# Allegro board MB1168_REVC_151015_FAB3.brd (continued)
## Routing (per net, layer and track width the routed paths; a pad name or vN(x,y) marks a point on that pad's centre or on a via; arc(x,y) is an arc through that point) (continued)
+3V3_PG: length 71.5
  TOP w0.127: U20.3 25.46,47.05 25.27,46.86 R148.2 25.53,45.59 26.29,46.35 29.08,46.35 30.86,48.13 49.4,48.13 50.67,46.86 75.82,46.86 76.45,46.23 87.76,46.23 90.17,43.81 R150.1
+3V3_STLINK: length 103.8
  TOP w0.203: 44.68,25.09 44.68,26.38 U24.9
  TOP w0.279: v1(40.26,25.27) 40.68,25.7 U24.1 ; U24.36 40.68,35.64 39.88,36.45 C97.2 ; C103.2 50.25,33.48 U24.24 ; U26.8 50.06,26.95 49.91,26.8 ; C107.2 36.62,27.98 U24.48
  TOP w0.508: v1(47.27,24.49) 47.27,23.9 C115.1 46.99,23.67 46,24.66 45.11,24.66 44.68,25.09 ; C107.2 v1(36.58,28.7) ; U16.5 24.2,60.51 C73.1 ; U16.5 22.28,61.01 ; U16.5 22.28,60.02 ; C73.1 v1(24.26,61.47) ; C73.1 23.67,60.45 ; C73.1 24.84,60.45 ; v1(52.82,15.63) 52.71,15.63 51.82,14.73 46.74,14.73 R208.2 37.97,13.72 JP13.1 ; C97.2 v1(39.88,37.72) ; C103.2 v1(50.29,34.39) ; 49.91,26.8 v1(49.91,26.04) ; T14.3 v1(99.95,16.51) ; R184.2 v1(45.85,21.79)
  BOTTOM w0.508: v1(45.85,21.79) 46.69,20.95 51.23,20.95 52.48,19.71 52.48,15.98 v1(52.82,15.63) 53.47,14.99 67.31,14.99 68.71,13.59 78.49,13.59 81.41,16.51 v1(99.95,16.51)
  vias: v1(25.27,61.59) v1(25.27,60.33)
+5V: length 70.9
  TOP w0.279: U28.8 28.79,20.36 29.72,19.43 C117.2
  TOP w0.508: LD7.1 v1(13.59,4.45) ; C82.1 96.95,44.58 ; C82.1 96.14,45.52 ; C82.1 95.33,44.58 ; C82.1 96.14,43.64 ; R156.1 v1(91.69,39.75) ; R151.1 v1(76.96,41.91) ; v1(17.27,49.53) 12.95,49.53 JP11.1 ; C79.1 21.08,51.74 ; C79.1 22.02,50.93 ; C79.1 20.14,50.93 ; C79.1 21.08,50.11 ; 96.18,42.63 U22.6 96.71,42.22 ; SB40.1 v1(88.64,29.09) ; 23.15,50.58 U20.6 23.56,51.12 ; D7.1 v1(31.9,31.51) ; TP22.1 R153.2 ; v1(22.61,43.05) 24.26,43.05 R148.1 ; C117.2 v1(30.61,18.8)
  BOTTOM w0.508: JP11.7 JP11.5 JP11.3 JP11.1 12.45,46.23 12.45,44.07 TP22.1 ; v1(30.61,18.8) 30.73,18.67 30.73,15.62 28.83,13.72 24.89,13.72 15.62,4.45 v1(13.59,4.45)
  vias: v1(18.03,49.53) v1(18.8,49.53) v1(95.89,46.23) v1(96.77,46.23)
AGND: length 24.7
  TOP w0.356: U4.4 107.66,140.93 v1(108.2,141.48) ; U3.4 v1(105.82,147.91)
  TOP w0.508: C9.2 106.05,144.7 ; C9.2 105.23,143.76 ; C9.2 106.86,143.76 ; C9.2 106.05,142.82 ; C19.2 v1(107.7,135.38) ; C17.1 v1(97.79,137.29) ; C18.2 v1(96.14,135.38) ; SB20.2 v1(105.54,130.05) ; SB3.2 v1(94.61,153.67) ; R23.2 v1(98.93,142.49) ; R21.2 v1(110.11,145.41) ; C8.1 v1(97.79,144.78) ; SB2.2 v1(94.61,156.46) ; C1.1 v1(112.27,156.21) ; 93.47,149.78 L1.2 ; L1.2 93.47,150.95 ; L1.2 v1(94.49,150.37) ; R16.2 v1(95.63,146.18) ; SB21.2 v1(108.46,130.05) ; SB19.2 v1(99.95,130.05) ; U1.1 v1(108.08,152.78) ; SB1.2 v1(94.49,160.15)
  vias: v1(93.73,163.07) v1(93.98,171.32) v1(100.71,150.24) v1(101.35,159.89) v1(101.98,171.2) v1(105.79,142.49) v1(106.93,142.49) v1(112.9,171.07) v1(113.16,159.38)
D5V: length 89
  TOP w0.508: v1(20.95,62.74) 20.95,62.36 20.57,61.98 17.27,61.98 16,60.71 14.48,60.71 12.57,58.8 10.29,58.8 v1(9.78,58.29) ; D5.1 8.13,54.6 8.13,53.21 v1(8.15,53.19) 8.13,53.16 8.13,50.8 9.65,49.28 9.65,46.99 11.05,45.59 JP11.2
  BOTTOM w0.508: v1(8.15,53.19) 8.13,53.21 8.13,56.64 v1(9.78,58.29) ; v1(20.95,62.74) 21.08,62.87 21.08,64.14 20.7,64.52 20.7,81.92 20.19,82.42 20.19,84.58 20.7,85.09 20.7,104.65 19.94,105.41 19.94,115.82 20.95,116.84 22.86,116.84 CN4.24
GND: length 585.9
  TOP w0.254: U17.4 31.74,55.84 v1(32,56.11) ; U12.4 93.32,94.55 93.32,93.9 v1(93.34,93.88) ; U17.3 31.24,55.86 v1(30.99,56.11) ; U19.4 39.74,55.13 v1(40.26,54.61) ; v1(35.81,57.4) 35.68,57.54 U18.6
  TOP w0.279: v1(63.25,137.03) 63.12,136.91 63.12,136.53 62.65,136.06 U5.27 ; v1(26.54,28.7) 26.84,28.41 U28.4 ; U25.8 v1(66.56,33.92) ; U5.74 49.39,121.79 47.88,121.79 v1(47.75,121.67) ; v1(62.48,118.11) 62.65,118.28 U5.99 ; U26.4 v1(52.2,29.45) ; U24.8 v1(44.18,27.8) ; U18.3 35.68,55.88 v1(35.94,56.13) 36.18,55.89 U18.4 ; U13.4 19.17,86.22 v1(19.3,86.36) ; U5.20 65.97,130.75 v1(66.29,130.43) 66.12,130.25 U5.19 ; v1(73.03,33.15) 72.86,32.98 U25.47 ; U24.35 41.18,35.9 40.89,36.2 C97.1 ; U10.2 v1(9.4,148.46) ; U25.23 64.23,28.48 v1(64.26,28.45) ; v1(37.85,28.83) 38.19,28.48 U24.47 ; v1(49.23,32.69) 48.93,32.98 U24.23 ; v1(69.85,25.27) 69.56,25.56 U25.35 ; U23.4 88.86,35.27 v1(89.15,35.56) ; U5.49 v1(51.65,133.57)
  TOP w0.305: U8.25 v1(90.29,102.25) ; U8.12 94.61,107.45 94.36,107.19 v1(94.36,107.19) ; v1(90.42,103.25) 90.13,103.55 U8.23 ; U7.4 v1(16.24,110.48) ; U8.4 v1(97.27,102.25) ; U7.25 v1(23.51,110.48) ; U7.12 v1(16.13,105.28) ; U7.23 23.88,109.18 23.5,109.56 v1(23.5,109.6)
  TOP w0.356: U21.4 v1(86.78,42.38) ; U15.2 v1(101.59,76.08)
  TOP w0.381: CN9.5 5.24,146.91 v1(5.59,146.56)
  TOP w0.457: U22.2 v1(94.74,41.27)
  TOP w0.508: 20.14,48.13 C79.2 ; C79.2 22.02,48.13 ; C79.2 21.08,47.32 ; C79.2 21.08,48.95 ; 103.96,123.9 CN7.10 ; CN7.10 105.28,126.37 ; CN7.10 105.28,121.44 ; CN7.10 106.6,123.9 ; 110.55,83.95 111.49,83.95 ; 110.55,83.95 110.55,83.01 ; 110.55,83.95 109.61,83.95 ; 110.55,83.95 110.55,84.89 ; R115.1 v1(100.97,63.75) ; 110.55,63.63 111.49,63.63 ; 110.55,63.63 110.55,64.57 ; 110.55,63.63 109.61,63.63 ; 110.55,63.63 110.55,62.69 ; CN4.1 22.43,146.05 ; CN4.1 20.75,146.05 ; CN4.1 21.59,146.89 ; CN4.1 21.59,145.21 ; CN12.18 110.55,67.11 ; CN12.18 110.55,65.23 ; CN12.18 109.61,66.17 ; CN12.18 111.49,66.17 ; 28.63,49.02 C81.2 ; C81.2 29.08,48.56 ; C81.2 29.54,49.02 ; 93.55,27.94 CN16.11 ; CN16.11 94.49,28.88 ; CN16.11 95.43,27.94 ; CN16.11 94.49,27 ; LD6.1 v1(49.14,13.58) ; R185.2 48.59,22.61 ; R185.2 47.68,22.61 ; R185.2 v1(48.13,21.82) ; 39.04,22.61 R182.1 ; R182.1 39.95,22.61 ; R182.1 v1(39.5,21.77) ; CN9.8 5.08,150.71 ; CN9.8 4.15,151.64 ; CN9.8 3.22,150.71 ; C101.1 78.74,32.89 v1(79.12,32.89) ; CN4.12 24.13,134.19 ; CN4.12 23.29,133.35 ; CN4.12 24.13,132.51 ; CN4.12 24.97,133.35 ; RV1.2 26.29,6.48 ; RV1.2 26.29,4.95 ; RV1.2 27.05,5.71 ; RV1.2 25.53,5.71 ; 109.61,81.41 CN12.6 ; CN12.6 110.55,82.35 ; CN12.6 111.49,81.41 ; CN12.6 110.55,80.47 ; CN11.5 v1(90.04,81.53) ; R169.1 v1(76.96,32.13) ; C80.2 28.25,48.64 ; C80.2 26.62,48.64 ; C80.2 27.43,47.89 ; C51.2 v1(99.31,102.62) ; C51.2 99.31,101.4 ; C51.2 99.77,101.85 ; 110.55,78.87 111.49,78.87 ; 110.55,78.87 110.55,79.81 ; 110.55,78.87 109.61,78.87 ; 110.55,78.87 110.55,77.93 ; 23.75,8.26 24.51,8.26 ; 23.75,8.26 23.75,9.02 ; 23.75,8.26 23.75,7.49 ; 23.75,8.26 22.99,8.26 ; CN16.12 97.97,27.94 ; CN16.12 97.03,27 ; CN16.12 96.09,27.94 ; CN16.12 97.03,28.88 ; R183.1 v1(40.77,21.41) ; R183.1 41.35,22.35 ; R183.1 40.18,22.35 ; R175.2 35.56,30.56 ; R175.2 35.56,29.64 ; R175.2 v1(34.67,30.1) ; CN4.11 21.59,134.19 ; CN4.11 22.43,133.35 ; CN4.11 21.59,132.51 ; CN4.11 20.75,133.35 ; SB20.1 v1(105.41,128.52) ; R74.1 8.64,147.14 ; R74.1 v1(9.78,146.56) ; R74.1 8.64,145.97 ; R167.2 v1(91.31,33.4) ; C115.2 47.45,22.61 ; C115.2 46.53,22.61 ; C115.2 v1(46.99,21.82) ; v1(72.14,125.22) 71.25,125.22 R46.1 ; C103.1 v1(51.31,34.39) ; v1(92.58,36.58) 93.85,36.58 v1(93.85,35.43) ; R113.1 101.73,66.75 ; R113.1 v1(100.97,66.29) ; R113.1 101.73,65.84 ; R172.2 v1(52.2,31.5) ; R76.2 v1(61.21,102.62) ; v1(72.39,126.24) C28.1 ; U29.4 51.56,45.21 v1(51.94,44.83) ; v1(75.31,126.75) 75.31,126.87 74.93,127.25 C27.2 ; B1.4 v1(50.1,5.52) ; B1.4 51.62,4.84 ; B1.4 52.56,5.52 ; B1.4 51.62,6.21 ; C93.1 v1(65.28,40.01) ; 22.6,152.53 U2.6 ; U2.6 23.67,152.98 ; U2.6 23.67,152.07 ; U2.6 v1(25.15,152.53) ; SW1.3 30.23,130.68 ; SW1.3 31.12,129.79 ; SW1.3 29.34,129.79 ; SW1.3 30.23,128.9 ; R123.2 v1(58.93,57.91) ; R206.2 v1(102.23,12.06) ; R206.2 101.78,12.83 ; R206.2 102.69,12.83 ; C36.2 36.18,115.95 ; C36.2 35.56,116.54 ; C36.2 35.56,115.37 ; C12.1 v1(56.39,145.29) ; 29.34,158.7 CN1.7 ; CN1.7 v1(27.69,159.38) ; CN1.7 30.66,159.38 ; CN1.7 29.34,160.07 ; C54.1 v1(40.64,42.67) ; R102.1 v1(49.53,76.83) ; C10.1 v1(53.34,145.29) ; 7.7,137.72 CN6.11 ; CN6.11 9.02,140.18 ; CN6.11 9.02,135.25 ; CN6.11 10.34,137.72 ; C89.1 v1(90.17,39.62) ; R173.1 35.56,31.7 ; R173.1 v1(34.67,31.24) ; R173.1 35.56,30.78 ; SB3.1 v1(90.68,153.67) ; C107.1 35.56,28.4 ; C107.1 35.56,27.48 ; C107.1 v1(34.67,27.94) ; v1(68.96,131.06) 69.09,130.94 69.85,130.94 ; C67.1 v1(15.62,86.23) ; C41.2 38.61,112.9 39.37,112.14 v1(39.5,112.14) ; C29.1 v1(42.67,124.08) ; v1(18.54,67.06) 18.54,66.42 R112.1 ; CN12.14 111.49,71.25 ; CN12.14 110.55,70.31 ; CN12.14 109.61,71.25 ; CN12.14 110.55,72.19 ; 92.53,44.58 C82.2 ; C82.2 93.34,43.64 ; C82.2 93.34,45.52 ; C82.2 94.16,44.58 ; CN7.5 103.89,117.98 ; CN7.5 103.89,115.85 ; CN7.5 105.08,116.92 ; CN7.5 102.69,116.92 ; C48.2 50.67,43.56 v1(51.18,44.07) ; C46.1 45.92,99.69 ; C46.1 45.01,99.69 ; C46.1 45.47,99.24 ; U2.4 v1(27.43,153.8) ; C113.1 v1(43.56,21.77) ; CN11.3 v1(90.04,82.8) ; 109.61,76.33 CN12.10 ; CN12.10 110.55,77.27 ; CN12.10 110.55,75.39 ; CN12.10 111.49,76.33 ; 103.96,98.86 CN7.11 ; CN7.11 105.28,96.39 ; CN7.11 105.28,101.32 ; CN7.11 106.6,98.86 ; 24.69,19.05 R196.2 ; R196.2 25.86,19.05 ; R196.2 v1(25.27,19.94) ; C24.2 70.99,130.18 v1(68.96,130.18) ; 8.26,150.11 8.71,150.11 ; 8.26,150.11 v1(8.26,150.88) ; 8.26,150.11 8.26,149.66 ; 35.58,39.24 CN15.2 ; CN15.2 36.52,38.3 ; CN15.2 36.52,40.18 ; C60.1 v1(98.81,97.03) ; C60.1 99.26,96.14 ; C60.1 98.81,95.68 ; v1(34.29,51.69) 34.29,52.32 C77.1 ; C31.2 v1(42.67,122.56) ; C57.2 v1(59.56,102.62) ; C35.1 v1(73.79,120.9) ; C106.1 v1(59.44,27.18) ; CN17.6 106.68,35.78 ; CN17.6 104.91,34.01 ; CN17.6 106.68,32.24 ; CN17.6 108.45,34.01 ; CN13.6 v1(13.64,66.88) ; U16.2 19.05,59.56 18.29,58.8 C74.2 v1(16.64,58.8) ; 106.43,46.05 TP21.1 ; TP21.1 105.49,46.99 ; TP21.1 106.43,47.93 ; TP21.1 107.37,46.99 ; C95.1 v1(67.44,38.99) ; LD5.2 v1(2.29,41.15) ; CN9.9 5.08,145.71 ; CN9.9 4.15,144.78 ; CN9.9 3.22,145.71 ; R109.1 v1(101.09,72.26) ; C88.2 v1(81.92,42.8) ; C65.2 13.08,88.7 ; C65.2 v1(13.08,86.36) ; C65.2 13.89,87.76 ; C65.2 12.27,87.76 ; C20.2 v1(71.12,135.64) ; 29.26,17.78 C117.1 ; C117.1 30.18,17.78 ; C117.1 v1(29.72,16.89) ; SB21.1 v1(108.46,128.52) ; CN12.16 111.49,68.71 ; CN12.16 110.55,67.77 ; CN12.16 109.61,68.71 ; CN12.16 110.55,69.65 ; L10.1 86.11,23.19 ; L10.1 86.73,22.61 ; L10.1 86.11,22.02 ; L10.1 v1(84.96,22.61) ; C96.2 27.74,37.72 ; C96.2 25.02,36.02 ; C96.2 25.02,39.42 ; C22.1 41.78,132.46 v1(40.89,133.35) ; U2.5 v1(25.15,153.8) ; U2.5 23.67,153.34 ; U2.5 22.6,153.8 ; U2.5 23.67,154.25 ; C109.2 v1(52.2,25.98) ; C25.2 73.28,128.14 v1(72.26,128.14) ; CN11.13 v1(90.04,76.45) ; C72.1 v1(37.97,62.23) ; CN6.10 9.02,115.14 ; CN6.10 9.02,110.21 ; CN6.10 10.34,112.67 ; CN6.10 7.7,112.67 ; 107.31,42.88 C86.1 106.86,42.42 ; U14.8 v1(4.57,82.04) ; v1(29.97,52.2) 29.46,52.7 C76.1 ; C37.1 v1(64.52,114.05) ; C78.1 v1(38.1,51.56) ; C108.2 v1(50.93,26.06) ; C64.1 16,87.5 v1(15.62,87.12) ; CN17.4 104.01,30.02 ; CN17.4 104.01,28.4 ; CN17.4 104.83,29.21 ; CN17.4 103.2,29.21 ; R57.2 v1(29.72,113.67) ; 1.45,143.93 CN9.7 2.58,144.71 ; B1.1 42.62,6.21 ; B1.1 42.62,4.84 ; B1.1 41.68,5.52 ; B1.1 v1(44.01,5.52) ; CN11.9 v1(90.04,78.99) ; CN9.11 v1(2.9,147.21) ; C66.1 v1(8.64,85.72) ; C70.1 v1(28.83,61.34) ; C14.1 v1(63.25,141.48) ; C58.2 v1(58.67,104.9) ; v1(58.04,107.95) R64.2 ; C118.1 v1(54.99,7.11) ; CN6.5 10.41,120.73 ; CN6.5 10.41,118.59 ; CN6.5 9.22,119.66 ; 36.07,108.79 C44.2 ; C44.2 36.07,110.67 ; C44.2 36.88,109.73 ; C44.2 35.25,109.73 ; v1(26.16,53.85) 25.78,54.23 R129.2 ; C83.2 107.24,44.32 ; C83.2 105.61,44.32 ; C83.2 106.43,45.26 ; C83.2 106.43,43.38 ; R124.2 v1(66.29,58.04) ; v1(64.64,41.4) C90.2 v1(63.37,42.67) ; CN11.11 v1(90.04,77.72) ; C69.1 v1(7.75,82.17) ; C26.1 v1(39.5,127.76) ; R66.2 v1(39.75,45.21) ; C73.2 v1(25.27,58.93) ; CN9.10 v1(2.92,149.21) ; R5.2 20.32,154 ; R5.2 v1(19.43,153.54) ; R5.2 20.32,153.09 ; R125.2 v1(75.82,57.91) ; R103.1 v1(52.07,76.71) ; C71.1 v1(33.91,62.23) ; R99.1 v1(99.44,81.79) ; C42.2 v1(14.61,110.39) ; U20.2 v1(24.51,49.15) ; v1(28.7,111.63) 28.07,111 C43.1 ; C94.1 v1(73.41,39.12) ; R127.2 v1(51.69,57.91) ; CN17.5 108.45,21.82 ; CN17.5 106.68,20.05 ; CN17.5 106.68,23.58 ; CN17.5 104.91,21.82 ; 44.25,22.61 C114.1 ; C114.1 45.16,22.61 ; C114.1 v1(44.7,21.77) ; C91.1 v1(59.05,38.61) ; C56.1 v1(89.81,97.54) ; C87.2 v1(78.61,42.8) ; R126.2 v1(83.95,57.02) ; U11.2 56.64,105.92 C47.2 v1(58.42,106.68) ; 13.08,83.01 C68.2 ; C68.2 12.27,83.95 ; C68.2 v1(13.08,85.22) ; C68.2 13.89,83.95 ; CN11.19 v1(90.04,72.64) ; 109.61,73.79 110.55,73.79 ; 110.55,73.79 110.55,72.85 ; 110.55,73.79 110.55,74.73 ; 110.55,73.79 111.49,73.79 ; 1.45,152.48 CN9.6 2.58,151.71 ; C34.2 v1(76.96,120.14) ; v1(28.19,57.28) C61.1 ; C75.2 v1(20.57,56.26) ; C62.1 v1(30.99,62.87) ; C5.1 v1(65.66,147.96) ; C3.1 20.32,150.44 ; C3.1 19.86,149.99 ; C3.1 v1(20.32,149.1) ; R174.2 v1(76.96,30.73) ; CN11.15 v1(90.04,75.18) ; C33.1 v1(45.85,121.92) ; C21.1 v1(68.83,133.99) ; R106.1 v1(73.28,75.69) ; C97.1 v1(40.89,37.72) ; C30.2 v1(76.96,124.84) ; U9.2 v1(56.77,99.06) ; CN11.17 v1(90.04,73.91) ; SB1.1 v1(90.68,160.15) ; C55.2 v1(84.07,100.33) ; C15.1 v1(77.09,140.46) ; U6.2 v1(35.56,112.65) ; R91.2 v1(9.02,87.12) ; C100.2 v1(90.55,35.56) ; 18.16,12.32 v1(19.05,12.32) ; CN13.9 v1(13.74,63.53) ; R215.2 v1(71.75,6.99) ; C92.2 94.74,39.5 ; C13.1 v1(49.91,140.46) ; SB19.1 v1(99.82,128.52) ; R104.1 v1(68.45,75.69) ; C59.2 v1(84.96,138.94) ; R105.2 v1(70.61,75.44) ; C2.1 v1(77.34,150.11) ; C116.2 v1(70.74,21.59) ; C11.1 v1(54.86,145.29) ; C63.2 v1(60.45,97.66) ; R203.1 v1(84.2,14.22) ; C32.2 v1(29.08,122.99) ; C39.2 28.07,112.52 v1(28.7,112.52) ; R107.1 v1(75.95,75.69) ; C4.1 v1(57.91,149.22) ; R157.2 v1(69.6,40.01) ; L1.1 v1(90.68,150.37) ; SB2.1 v1(90.68,156.46) ; C52.1 v1(84.07,101.6) ; C104.2 v1(80.77,31.24) ; C84.1 v1(43.43,56.26) ; C99.1 v1(75.56,35.81) ; C112.1 v1(42.04,21.79) ; R147.2 v1(22.73,44.07)
  BOTTOM w0.508: 104.91,21.82 CN17.5 ; CN17.5 108.45,21.82 ; CN17.5 106.68,20.05 ; CN17.5 106.68,23.58 ; CN12.6 110.55,82.35 ; CN12.6 111.49,81.41 ; CN12.6 110.55,80.47 ; CN12.6 109.61,81.41 ; 103.96,98.86 CN7.11 ; CN7.11 106.6,98.86 ; CN7.11 105.28,96.39 ; CN7.11 105.28,101.32 ; 104.01,28.4 CN17.4 ; CN17.4 104.83,29.21 ; CN17.4 104.01,30.02 ; CN17.4 103.2,29.21 ; 11.63,41.15 TP23.1 ; TP23.1 13.51,41.15 ; TP23.1 12.57,40.21 ; TP23.1 12.57,42.09 ; 1.45,143.93 CN9.7 ; CN9.7 1.45,145.48 ; CN9.7 2.58,144.71 ; L8.6 9.1,35.67 ; L8.6 10.27,34.5 ; L8.6 7.94,34.5 ; L8.6 9.1,33.34 ; L8.4 7.77,32 ; L8.4 6.6,33.17 ; L8.4 5.44,32 ; L8.4 6.6,30.84 ; 94.49,27 CN16.11 ; CN16.11 94.49,28.88 ; CN16.11 93.55,27.94 ; CN16.11 95.43,27.94 ; 3.22,145.71 CN9.9 ; CN9.9 4.15,144.78 ; CN9.9 5.08,145.71 ; CN9.9 4.15,146.64 ; CN17.6 108.45,34.01 ; CN17.6 106.68,32.24 ; CN17.6 106.68,35.78 ; CN17.6 104.91,34.01 ; 109.61,63.63 110.55,63.63 ; 110.55,63.63 110.55,62.69 ; 110.55,63.63 110.55,64.57 ; 110.55,63.63 111.49,63.63 ; 89.33,146.05 CN5.1 ; CN5.1 90.17,146.89 ; CN5.1 91.01,146.05 ; 109.61,66.17 CN12.18 ; CN12.18 111.49,66.17 ; CN12.18 110.55,65.23 ; CN12.18 110.55,67.11 ; CN15.2 36.52,40.18 ; CN15.2 36.52,38.3 ; CN15.2 37.46,39.24 ; CN15.2 35.58,39.24 ; CN19.2 69.57,19.05 ; CN19.2 68.63,18.11 ; CN19.2 67.69,19.05 ; CN19.2 68.63,19.99 ; 106.43,46.05 TP21.1 ; TP21.1 107.37,46.99 ; TP21.1 106.43,47.93 ; TP21.1 105.49,46.99 ; 7.7,112.67 CN6.10 ; CN6.10 10.34,112.67 ; CN6.10 9.02,110.21 ; CN6.10 9.02,115.14 ; 110.55,78.87 110.55,79.81 ; 110.55,78.87 111.49,78.87 ; 110.55,78.87 109.61,78.87 ; 110.55,78.87 110.55,77.93 ; L8.5 2.77,32 ; L8.5 1.6,33.17 ; L8.5 1.6,30.84 ; CN9.8 5.08,150.71 ; CN9.8 4.15,151.64 ; CN9.8 4.15,149.78 ; CN9.8 3.22,150.71 ; 1.45,150.93 CN9.6 ; CN9.6 2.58,151.71 ; CN9.6 1.45,152.48 ; 25.53,5.71 RV1.2 ; RV1.2 26.29,6.48 ; RV1.2 26.29,4.95 ; RV1.2 27.05,5.71 ; CN12.10 111.49,76.33 ; CN12.10 109.61,76.33 ; CN12.10 110.55,77.27 ; CN12.10 110.55,75.39 ; 92.71,145.21 CN5.2 ; CN5.2 91.87,146.05 ; CN5.2 93.55,146.05 ; CN5.2 92.71,146.89 ; CN6.11 10.34,137.72 ; CN6.11 9.02,135.25 ; CN6.11 7.7,137.72 ; CN6.11 9.02,140.18 ; 23.75,7.49 23.75,8.26 ; 23.75,8.26 22.99,8.26 ; 23.75,8.26 23.75,9.02 ; 23.75,8.26 24.51,8.26 ; CN4.1 21.59,146.89 ; CN4.1 21.59,145.21 ; CN4.1 20.75,146.05 ; CN4.1 22.43,146.05 ; CN16.12 97.97,27.94 ; CN16.12 96.09,27.94 ; CN16.12 97.03,28.88 ; CN16.12 97.03,27 ; 109.61,83.95 110.55,83.95 ; 110.55,83.95 110.55,84.89 ; 110.55,83.95 110.55,83.01 ; 110.55,83.95 111.49,83.95 ; 110.55,73.79 110.55,74.73 ; 110.55,73.79 110.55,72.85 ; 110.55,73.79 111.49,73.79 ; 110.55,73.79 109.61,73.79 ; CN7.10 105.28,126.37 ; CN7.10 103.96,123.9 ; CN7.10 105.28,121.44 ; CN7.10 106.6,123.9 ; 103.89,115.85 CN7.5 ; CN7.5 103.89,117.98 ; CN7.5 105.08,116.92 ; CN7.5 102.69,116.92 ; 109.61,71.25 CN12.14 ; CN12.14 110.55,70.31 ; CN12.14 110.55,72.19 ; CN12.14 111.49,71.25 ; 109.61,68.71 CN12.16 ; CN12.16 111.49,68.71 ; CN12.16 110.55,69.65 ; CN12.16 110.55,67.77 ; CN6.5 11.61,119.66 ; CN6.5 9.22,119.66 ; CN6.5 10.41,120.73 ; CN6.5 10.41,118.59
  vias: v1(1.04,44.35) v1(0.97,27.43) v1(1.24,57.89) v1(1.17,1.27) v1(1.42,153.01) v1(1.63,108.15) v1(1.63,91.19) v1(1.75,123.29) v1(1.78,73.94) v1(10.87,1.3) v1(14.99,146.69) v1(15.62,148.97) v1(17.27,143.76) v1(17.27,139.7) v1(17.27,134.49) v1(18.03,129.54) v1(18.92,171.32) v1(19.3,144.91) v1(19.43,137.29) v1(19.43,132.08) v1(20.19,46.86) v1(20.95,46.86) v1(21.84,46.86) v1(22.1,101.09) v1(22.1,96.9) v1(22.53,1.09) v1(23.62,49.66) v1(23.62,48.64) v1(24.64,101.09) v1(24.64,96.9) v1(25.15,40.13) v1(25.15,35.18) v1(25.4,49.66) v1(25.4,48.64) v1(26.04,40.13) v1(26.16,35.18) v1(27.18,101.09) v1(27.18,96.9) v1(28.45,129.54) v1(29.72,101.09) v1(29.72,96.9) v1(30.35,126.79) v1(31.11,171.45) v1(32.26,101.09) v1(32.26,96.9) v1(33.5,145.41) v1(34.8,101.09) v1(34.8,96.9) v1(35.1,113.51) v1(35.05,111.79) v1(35.2,9.27) v1(36.02,113.54) v1(36.04,111.81) v1(36.83,115.95) v1(37.24,1.09) v1(37.34,101.09) v1(37.34,96.9) v1(42.77,136.73) v1(42.95,19.46) v1(42.98,17.02) v1(44.07,171.58) v1(46,144.32) v1(46.61,98.81) v1(51.44,16.33) v1(51.82,1.17) v1(51.97,21.64) v1(56.13,171.58) v1(70.61,171.58) v1(71.37,1.07) v1(75.95,129.16) v1(77.09,122.56) v1(84.91,1.07) v1(87.25,9.78) v1(89.92,171.32) v1(90.17,64.14) v1(92.96,46.1) v1(93.85,46.1) v1(94.23,42.16) v1(94.23,40.39) v1(95.25,42.16) v1(95.25,40.39) v1(95.63,9.78) v1(100.13,115.16) v1(100.2,13.34) v1(100.94,70.13) v1(105,1.37) v1(112.73,1.3) v1(112.95,23.83) v1(113.08,126.14) v1(113.11,13.84) v1(113.23,106.12) v1(113.23,90.07) v1(113.39,57.78) v1(113.39,45.57) v1(113.39,33.17)
VDD: length 154.3
  TOP w0.254: v1(31.5,57.45) 31.55,57.45 31.74,57.65 U17.5 ; U25.1 70.06,35.52 70.61,36.07 ; 72.9,33.91 72.47,33.48 U25.48 ; U19.5 39.74,59.04 v1(39.88,59.18)
  TOP w0.279: C109.1 53.21,27.8 U26.1 ; C76.2 30.24,54.75 U17.1 ; C77.2 34.68,53.73 U18.1 ; v1(18.92,87.62) 19.17,87.86 U13.5 ; C116.1 70.48,23.88 70.48,25.65 70.06,26.08 U25.36 ; U28.3 v1(27.49,28.76) ; U12.1 93.1,96.13 91.69,97.54 C56.2 ; v1(92.71,93.09) 94.71,93.09 U12.5 ; U13.1 16.91,85.49 C67.2 ; U25.24 60.54,27.98 C106.2 ; U23.8 82.97,33.31 C104.1 ; U19.1 38.24,53.73 C78.2 ; v1(50.93,29.45) U26.5 ; U28.5 v1(26.84,22.86)
  TOP w0.508: CN5.26 96.77,119.63 R43.1 ; C104.1 v1(81.79,31.24) ; T10.4 78.87,56.12 78.87,57.61 ; T7.1 74.17,58.68 ; T7.1 74.63,57.61 ; T7.1 73.71,57.61 ; T7.2 72.9,58.68 ; T7.2 73.36,57.61 ; T7.2 72.44,57.61 ; JP10.1 103.38,55.68 ; JP10.1 104.32,54.74 ; JP10.1 102.44,54.74 ; JP10.1 103.38,53.8 ; v1(74.55,35.81) C99.2 73.91,34.92 72.9,33.91 ; L6.2 108.46,41.61 ; L6.2 109.08,41.02 ; L6.2 108.46,40.44 ; C109.1 v1(53.21,25.98) ; v1(57.02,20.07) 57.02,10.29 v1(56.26,9.53) ; 109.47,37.41 TP25.1 ; TP25.1 108.53,38.35 ; TP25.1 110.41,38.35 ; TP25.1 109.47,39.29 ; R139.2 v1(39.5,51.44) ; C67.2 v1(15.62,85.22) ; R3.2 v1(22.61,156.84) ; v1(91.54,98.27) C56.2 ; v1(71.37,24.77) 71.25,24.64 71.25,24.13 C116.1 ; 20.07,151.76 v1(18.8,151.76) ; T7.3 71.63,56.12 T8.4 ; T7.3 71.63,59.05 ; T7.3 72.09,57.61 ; T7.3 71.17,57.61 ; 78.87,57.61 79.32,57.61 ; 78.87,57.61 78.41,57.61 ; 78.87,57.61 78.87,58.68 ; R117.2 v1(35.05,62.23) ; 17.91,82.17 19.05,82.17 19.05,81.53 v1(19.3,81.28) ; 108.33,41.96 108.33,42.42 ; 108.33,42.42 108.79,42.42 ; 108.33,42.42 108.33,42.88 ; C77.2 34.04,54.1 v1(34.04,54.48) ; R89.2 90.53,91.29 v1(90.55,91.26) ; R100.2 v1(103.89,81.92) ; v1(90.3,50.42) 90.3,50.29 90.87,49.72 T11.3 ; v1(73.41,38.1) C94.2 72.26,37.72 70.61,36.07 ; B2.4 B2.1 57.72,5.52 56.26,6.99 v1(56.26,9.53) ; R192.2 v1(72.14,24.89) ; CN1.5 v1(31.24,161.93) ; R178.1 v1(53.98,29.34) ; 109.22,43.38 C83.1 ; C83.1 110.03,44.32 ; C83.1 108.41,44.32 ; C83.1 109.22,45.26 ; C78.2 v1(37.34,53.59) ; v1(30.1,53.09) 29.46,53.72 C76.2 ; R213.2 v1(56.26,9.53) ; T9.1 81.41,58.68 ; T9.1 80.95,57.61 ; T9.1 81.86,57.61 ; 79.68,57.61 T9.2 ; T9.2 80.14,58.68 ; T9.2 80.59,57.61 ; R155.1 v1(67.44,40.51) ; C106.2 v1(60.45,27.18) ; v1(32.38,153.42) 32.89,152.91 R6.1 ; R122.2 v1(43.94,59.05) ; R108.2 v1(101.47,74.8) ; U2.8 C3.2 v1(21.34,149.1) ; R136.2 30.86,51.69 v1(30.61,51.44) ; v1(59.05,39.62) C91.2 60.2,39.88 L7.1 ; v1(90.04,84.07) CN11.1 ; R53.2 v1(78.49,116.08) ; R83.2 v1(89.81,96.27) ; R56.2 v1(78.49,114.55) ; R186.1 v1(49.28,21.77)
  BOTTOM w0.508: v1(27.49,28.76) 27.49,27.36 26.84,26.71 v1(26.84,22.86)
VDD_ADJ: length 13.5
  TOP w0.508: 103.38,37.29 JP12.3 ; JP12.3 102.44,38.23 ; JP12.3 104.32,38.23 ; JP12.3 103.38,39.17 ; R154.1 99.52,40.26 ; R154.1 98.35,40.26 ; R154.1 98.93,39.69 ; 95.63,35.76 C98.1 ; C98.1 95.63,37.39 ; C98.1 96.38,36.58 ; TP24.1 106.3,39.29 ; TP24.1 106.3,37.41 ; TP24.1 105.36,38.35 ; TP24.1 107.24,38.35 ; 96.22,38.73 C92.1 95.76,38.28 ; 96.71,40.33 U22.4 96.18,39.92
VDD_ANA: length 20.4
  TOP w0.356: 101.39,138.98 U4.8
  TOP w0.508: C8.2 99.69,145.24 ; C8.2 99.69,144.32 ; C8.2 100.15,144.78 ; C18.1 101.02,135.38 ; C18.1 100.2,134.44 ; C18.1 99.39,135.38 ; C18.1 100.2,136.32 ; R15.1 v1(111.63,145.54) ; R43.2 96.77,130.62 ; R43.2 96.19,130.05 ; R43.2 97.36,130.05 ; C17.2 100.15,137.29 ; C17.2 99.69,137.74 ; C17.2 99.69,136.83 ; U1.3 C1.2 v1(111.25,156.21) ; 102.44,143.76 103.25,143.76 ; 103.25,143.76 103.25,144.7 ; 103.25,143.76 103.25,142.82 ; R44.2 98.17,130.62 ; R44.2 98.76,130.05 ; R44.2 97.59,130.05 ; R22.2 v1(111.63,143.89) ; 102.41,145.61 U3.8 ; U3.8 103.19,145.96 ; U3.8 101.64,145.96
  vias: v1(100.2,133.48) v1(100.2,132.72) v1(100.97,133.48) v1(100.97,132.72) v1(102.49,142.37) v1(103.38,142.37)
VDD_MCU: length 159.8
  TOP w0.279: 62.15,136.35 U5.28 ; U5.100 63.15,117.7 ; 51.18,136.78 51.15,136.75 U5.50 ; U5.73 46.4,122.25 44.58,124.08
  TOP w0.508: v1(76.83,26.29) R180.2 ; v1(75.31,125.73) 74.68,125.09 R47.1 74.42,125.22 C28.2 ; 44.58,124.08 v1(44.58,123.06) ; v1(64.52,115.06) C37.2 63.63,117.22 63.15,117.7 ; v1(50.04,139.45) C13.2 51.18,139.19 51.18,136.78 ; 62.15,136.35 62.15,136.95 63.25,138.05 C14.2 v1(64.14,139.45) ; v1(73.28,113.67) v1(97.16,113.67)
  BOTTOM w0.508: v1(97.16,113.67) 97.16,112.27 100.43,108.99 100.43,96.67 105.33,91.77 105.33,54.15 JP10.2 101.55,50.37 101.55,48.56 97.66,44.68 97.66,35.81 92.46,30.61 83.44,30.61 79.12,26.29 v1(76.83,26.29)
VDD_PG: length 134.9
  TOP w0.127: U22.3 93.34,40.29 93.34,38.86 R156.2 v1(93.22,37.85) ; v1(53.34,45.47) 66.67,45.47 67.82,44.32 81.92,44.32 v1(82.93,43.31) ; R60.1 38.48,107.31 v1(38.35,107.19)
  BOTTOM w0.127: v1(93.22,37.85) 84.58,37.85 82.93,39.5 v1(82.93,43.31) ; v1(53.34,45.47) 50.04,45.47 41.66,53.85 39.5,53.85 38.48,54.86 36.07,54.86 34.42,56.52 34.42,62.61 33.85,63.18 32.7,63.18 30.86,65.02 27.3,65.02 25.53,66.8 25.53,89.38 32.82,96.67 32.82,98.4 38.35,103.94 v1(38.35,107.19)
VDD_USB: length 17.4
  TOP w0.305: C33.2 48.13,120.9 48.48,121.25 U5.75
  TOP w0.508: JP7.2 35.33,122.71 40.49,122.71 TP7.1 42.16,121.03 C31.1 43.81,120.9 C33.2
VDDA: length 14.3
  TOP w0.279: U5.22 66.6,131.75 67.31,132.46
  TOP w0.508: JP4.2 TP5.1 73.91,135.64 71.5,133.22 C20.1 70.1,133.22 C21.2 67.82,132.97 67.31,132.46
AIN_1: length 6.2
  TOP w0.127: R186.2 R185.1 48.06,23.7 48.06,24.51 47.35,25.22 45.59,25.22 45.18,25.63 U24.10
BOOT0: length 75.2
  TOP w0.127: v1(52.07,124.71) 52.07,123.83 52.7,123.19 57.53,123.19 60.15,120.57 U5.94 60.15,116.61 63.35,113.41 68.45,113.41 72.26,117.22 86.74,117.22 CN5.21 ; v1(39.24,130.68) 38.35,130.68 36.32,132.72 R36.1 JP3.1
  BOTTOM w0.127: v1(39.24,130.68) 41.27,132.72 46.86,132.72 49.15,130.43 49.15,126.11 50.8,124.46 51.82,124.46 v1(52.07,124.71)
CAL: length 33
  TOP w0.127: T7.4 70.36,56.39 v1(69.98,56.01) ; v1(68.58,37.21) 69.09,36.7 69.09,35.11 U25.3 ; R125.1 v1(75.06,56.01) 73.91,56.01 T8.3
  BOTTOM w0.127: v1(69.98,56.01) v1(75.06,56.01) 75.44,55.63 75.44,49.91 68.58,43.05 v1(68.58,37.21)
CAL_D: length 69.4
  TOP w0.356: U21.3 86.29,41.73 85.85,42.16
  TOP w0.508: T6.4 62.1,56.12 T5.3 ; 74.7,54.04 T8.1 72.99,54.04 ; T3.3 55.19,57.61 ; T3.3 54.74,56.12 T4.4 ; T3.3 54.74,58.68 ; T3.2 56.01,58.68 ; T3.2 56.46,57.61 ; T3.2 55.55,57.61 ; R133.2 75.95,54.8 ; R133.2 76.53,54.23 ; R133.2 75.36,54.23 ; 72.3,54.99 T8.5 70.59,54.99 ; T1.3 47.37,58.68 ; T1.3 47.37,56.12 T2.4 ; T1.3 47.83,57.61 ; 56.82,57.61 T3.1 ; T3.1 57.73,57.61 ; T3.1 57.28,58.68 ; T7.5 70.82,52.37 ; T7.5 70.36,51.3 ; T7.5 70.36,53.43 ; T7.5 69.9,52.37 ; 64.19,57.61 T5.1 ; T5.1 64.64,58.68 ; T5.1 65.1,57.61 ; 85.85,42.16 85.85,44.2 85.09,44.96 68.71,44.96 v1(68.07,45.59) ; 49.45,57.61 T1.1 ; T1.1 49.91,58.68 ; T1.1 50.37,57.61 ; 71.17,52.37 T7.6 ; T7.6 71.63,51.3 ; T7.6 72.09,52.37 ; 70.59,54.04 T8.6 72.3,54.04 ; 73.71,52.37 T7.8 ; T7.8 74.17,51.3 ; T7.8 74.63,52.37 ; 62.92,57.61 T5.2 ; T5.2 63.37,58.68 ; T5.2 63.83,57.61 ; T1.2 48.64,58.68 ; T1.2 48.18,57.61 ; T1.2 49.1,57.61 ; T7.7 72.9,53.43 ; T7.7 72.9,51.3 ; T7.7 73.36,52.37 ; T7.7 72.44,52.37 ; 72.99,54.99 T8.2 74.7,54.99 ; T5.3 62.1,58.68 ; T5.3 62.56,57.61
  BOTTOM w0.508: v1(67.94,51.94) 67.94,45.72 v1(68.07,45.59)
E5V: length 32.1
  TOP w0.508: JP11.8 4.7,46.35 4.7,48.77 3.84,49.63 D3.1 ; L8.3 4.1,35.67 ; L8.3 5.27,34.5 ; L8.3 2.93,34.5 ; L8.3 4.1,33.34 ; 15.95,37.72 C96.1 ; C96.1 18.67,36.02 ; C96.1 18.67,39.42
  BOTTOM w0.508: JP11.8 3.43,42.04 4.06,41.4 4.06,34.54 L8.3
IDD_MEAS: length 20.6
  TOP w0.127: U25.25 64.56,27.09 66.29,28.83 66.29,29.72 73.03,36.45 75.82,36.45 77.22,35.05 C101.2 79.12,35.05 R164.1
IRDA_RX: length 47.8
  TOP w0.127: v1(25.76,90.96) 25.4,91.31 3.81,91.31 3.05,90.55 3.05,87.25 3.46,86.83 U14.4
  BOTTOM w0.127: v1(25.76,90.96) 31.37,96.57 31.37,98.63 36.2,103.45 JP9.1
LC_H: length 31.2
  TOP w0.127: SB29.1 37.85,99.57 16.26,99.57 C40.2 13.76,102.06 L2.4 11,102.06 9.45,100.51 L3.2
LC_L: length 31.1
  TOP w0.127: SB30.1 37.85,98.42 16.13,98.42 C40.1 13.76,96.06 L2.1 11,96.06 9.45,97.61 L3.1
LCDCOM0: length 49.6
  TOP w0.127: v1(48.01,125.73) 48.48,125.25 U5.67
  BOTTOM w0.127: v1(48.01,125.73) 46.99,124.71 46.99,120.9 41.91,115.82 41.91,112.65 39.37,110.11 39.37,101.85 35.69,98.17 35.69,96.6 28.32,89.23 28.32,87.15 CN10.3
LCDCOM1: length 50.7
  TOP w0.127: U5.68 48.09,124.75 v1(47.12,125.73)
  BOTTOM w0.127: v1(47.12,125.73) 46.61,125.22 46.61,121.16 41.53,116.08 41.53,112.9 38.99,110.36 38.99,103.81 33.43,98.25 33.43,96.52 27.69,90.78 27.69,87.25 26.7,86.26 CN10.1
LCDCOM2: length 48.7
  TOP w0.127: U5.69 50.5,124.25 v1(51.69,123.06)
  BOTTOM w0.127: v1(51.69,123.06) 51.69,122.3 50.93,121.54 49.53,121.54 43.43,115.44 43.43,112.39 40.64,109.6 40.64,99.31 32.89,91.57 32.89,87.34 CN10.5
LCDCOM3: length 58
  TOP w0.127: v1(52.96,123.7) 53.09,123.57 59.69,123.57 61.15,122.11 U5.96
  BOTTOM w0.127: v1(52.96,123.7) 52.96,123.06 51.05,121.16 50.16,121.16 43.94,114.94 43.94,112.27 41.02,109.35 41.02,99.06 33.27,91.31 33.27,87.25 34.29,86.23 CN10.7
LCDCOM4: length 59.2
  TOP w0.127: U5.78 52.15,118.57 51.94,118.36 51.69,118.36 v1(51.56,118.24)
  BOTTOM w0.127: CN14.7 35.31,69.44 35.31,78.74 40.26,83.69 40.26,94.61 44.96,99.31 44.96,104.14 46.48,105.66 46.48,114.17 50.55,118.24 v1(51.56,118.24)
LCDCOM5: length 63.3
  TOP w0.127: U5.79 52.65,120.96 v1(52.58,121.03)
  BOTTOM w0.127: CN14.5 33.15,69.82 33.15,77.6 37.72,82.17 37.72,93.34 44.07,99.69 44.07,110.11 45.34,111.38 45.34,114.17 50.67,119.51 51.69,119.51 52.58,120.4 v1(52.58,121.03)
LCDCOM6: length 69
  TOP w0.127: U5.80 53.15,121.35 52.58,121.92 51.18,121.92 v1(50.8,122.3)
  BOTTOM w0.127: v1(50.8,122.3) 49.66,122.3 42.93,115.57 42.93,112.52 40.26,109.86 40.26,101.5 36.69,97.93 36.69,96.13 30.73,90.17 30.73,79.25 28.07,76.58 28.07,69.63 CN14.3
LCDCOM7: length 71.4
  TOP w0.127: v1(50.8,123.06) 51.56,122.3 53.47,122.3 54.65,121.12 U5.83
  BOTTOM w0.127: CN14.1 27.69,69.44 27.69,76.71 30.23,79.25 30.23,90.17 36.22,96.16 36.22,98.07 39.75,101.6 39.75,109.86 42.42,112.52 42.42,115.57 49.91,123.06 v1(50.8,123.06)
LCDSEG0: length 87.2
  TOP w0.127: v1(71.75,143.89) 70.61,143.89
  BOTTOM w0.127: v1(71.75,143.89) 71.75,143.64 70.1,141.99 70.1,120.9 71.63,119.38 73.41,119.38 76.33,116.46 76.33,114.94 85.09,106.17 85.09,93.85 88.27,90.68 88.27,84.07 86.49,82.3 86.49,69.72 85.22,68.45 CN14.47
LCDSEG1: length 67
  TOP w0.127: SB9.1 64.26,144.27 62.48,142.49 62.48,139.32 61.85,138.68 61.09,138.68 59.31,136.91 v1(59.31,136.27)
  BOTTOM w0.127: v1(59.31,136.27) 59.18,136.14 59.18,134.37 59.82,133.73 59.82,132.84 60.83,131.83 61.72,131.83 65.15,128.4 65.15,106.93 64.52,106.3 64.52,97.54 68.83,93.22 68.83,87.28 CN10.35
LCDSEG2: length 53.7
  TOP w0.127: v1(61.85,130.94) 61.85,131.06 63.15,132.36 U5.26
  BOTTOM w0.127: CN10.33 68.41,87.3 68.41,92.5 64.01,96.9 64.01,106.68 64.64,107.31 64.64,112.27 63.63,113.28 63.63,115.19 64.52,116.08 64.52,128.27 v1(61.85,130.94)
LCDSEG3: length 56.1
  TOP w0.127: v1(61.34,133.48) 61.21,133.48 60.65,134.04 U5.31
  BOTTOM w0.127: CN10.41 75.95,87.79 75.95,90.3 67.18,99.06 67.18,105.92 67.56,106.3 67.56,114.94 65.91,116.59 65.91,128.65 61.34,133.22 v1(61.34,133.48)
LCDSEG4: length 24.1
  TOP w0.127: CN10.39 76.07,87.34 76.07,90.3 76.83,91.06 SB28.2 76.83,104.01 JP14.2 77.72,104.9 JP1.1
LCDSEG5: length 76.8
  TOP w0.127: v1(58.8,137.16) 60.33,138.68 SB14.2 ; JP14.1 75.31,104.01 SB28.1 74.42,101.09 67.06,101.09 SB34.1 66.17,104.01 JP16.1
  BOTTOM w0.127: CN10.37 71.12,87.53 71.12,92.2 65.66,97.66 JP16.1 65.66,105.28 67.18,106.81 67.18,114.55 65.53,116.2 65.53,128.52 61.85,132.21 61.09,132.21 60.58,132.72 60.58,135.76 59.18,137.16 v1(58.8,137.16)
LCDSEG6: length 68.8
  TOP w0.127: v1(57.91,138.18) 57.91,139.32
  BOTTOM w0.127: CN10.47 85.09,86.23 84.07,87.25 84.07,90.68 81.03,93.73 81.03,104.78 79.38,106.43 77.6,106.43 76.2,107.82 76.2,110.62 75.82,111 73.15,111 67.06,117.09 67.06,132.21 64.01,135.25 61.47,135.25 59.05,137.67 58.42,137.67 v1(57.91,138.18)
LCDSEG7: length 69.4
  TOP w0.127: v1(51.94,82.04) 78.39,82.04 CN10.45 ; SB35.2 56.13,114.05 56.77,113.41 v1(57.78,113.41)
  BOTTOM w0.127: v1(57.78,113.41) 57.78,110.24 56.77,109.22 56.77,100.84 51.05,95.12 51.05,82.93 v1(51.94,82.04)
LCDSEG8: length 29.3
  TOP w0.127: JP15.1 68.71,105.03 JP16.2 67.69,104.01 SB34.2 v1(68.96,101.98)
  BOTTOM w0.127: CN10.43 78.61,87.66 78.61,89.92 68.96,99.57 v1(68.96,101.98)
LCDSEG9: length 47.5
  TOP w0.127: U5.91 58.65,121.18 57.78,122.05 55.24,122.05 v1(55.12,121.92)
  BOTTOM w0.127: CN10.13 42.04,86.23 42.8,87 42.8,95.76 46.1,99.06 46.1,103.89 47.24,105.03 47.24,113.79 50.67,117.22 51.82,117.22 54.74,120.14 54.74,121.54 v1(55.12,121.92)
LCDSEG10: length 56.9
  TOP w0.127: v1(53.09,132.33) 52.65,132.77 U5.47
  BOTTOM w0.127: CN10.11 39.37,86.23 38.35,87.25 38.35,93.34 44.58,99.57 44.58,104.39 46.1,105.92 46.1,114.3 50.67,118.87 51.82,118.87 53.98,121.03 53.98,131.44 v1(53.09,132.33)
LCDSEG11: length 58.2
  TOP w0.127: v1(51.69,132.59) 52.15,133.05 U5.48
  BOTTOM w0.127: v1(51.69,132.59) 53.59,130.68 53.59,122.81 52.07,121.28 52.07,120.52 51.56,120.02 50.55,120.02 44.83,114.3 44.83,111.51 43.69,110.36 43.69,100.08 35.69,92.08 35.69,87.38 36.83,86.23 CN10.9
LCDSEG12: length 69.9
  TOP w0.127: SB5.2 v1(47.88,144.27)
  BOTTOM w0.127: CN10.19 48.51,87.28 48.51,93.98 55.88,101.35 55.88,109.6 56.77,110.49 56.77,118.62 57.28,119.13 57.28,130.56 59.18,132.46 59.18,133.48 57.91,134.75 57.91,136.53 50.16,144.27 v1(47.88,144.27)
LCDSEG13: length 87.4
  TOP w0.127: v1(46.1,130.94) 46.1,131.19 SB16.2 ; v1(21.72,83.19) 45.09,83.19 47.02,85.12 CN10.17
  BOTTOM w0.127: v1(21.72,83.19) 21.97,83.44 21.97,92.99 25.22,96.24 25.22,97.99 26.47,99.24 26.47,101.47 28.45,103.45 28.45,108.84 35.43,115.82 35.43,116.33 38.48,119.38 38.48,124.46 44.96,130.94 v1(46.1,130.94)
LCDSEG14: length 58.5
  TOP w0.127: U5.53 51.01,132.25 51.69,131.57 v1(55.5,131.57)
  BOTTOM w0.127: CN10.15 45.59,87.34 45.59,93.09 49.78,97.28 49.78,103.12 48.39,104.52 48.39,113.16 51.18,115.95 52.2,115.95 56.13,119.89 56.13,130.94 v1(55.5,131.57)
LCDSEG15: length 59.3
  TOP w0.127: U5.54 50.75,131.75 51.44,131.06 56.01,131.06 56.9,131.95 59.69,131.95 v1(60.45,131.19)
  BOTTOM w0.127: CN10.25 58.42,87.47 58.42,94.57 58.93,95.08 58.93,103.38 59.94,104.39 59.94,120.52 60.71,121.28 60.71,125.22 59.56,126.36 59.56,130.3 v1(60.45,131.19)
LCDSEG16: length 40.6
  TOP w0.127: v1(59.69,121.92) 60.65,120.96 U5.95
  BOTTOM w0.127: CN10.23 55.63,87.22 55.63,94.36 58.04,96.77 58.04,105.28 59.05,106.3 59.05,121.28 v1(59.69,121.92)
LCDSEG17: length 68.1
  TOP w0.127: CN10.21 52.1,83.85 49.78,81.53 v1(35.31,81.53) ; v1(51.56,120.9) 51.65,120.82 U5.77
  BOTTOM w0.127: v1(35.31,81.53) 35.31,92.46 41.4,98.55 41.4,108.97 44.32,111.89 44.32,114.43 50.55,120.65 51.31,120.65 v1(51.56,120.9)
LCDSEG18: length 41.4
  TOP w0.127: JP17.1 55.63,111.12 v1(61.21,111.12) ; SB36.2 52.83,105.03 JP18.2
  BOTTOM w0.127: CN10.31 63.75,87.28 63.75,93.85 62.48,95.12 62.48,106.3 61.85,106.93 61.85,108.71 61.21,109.35 v1(61.21,111.12) ; JP18.2 52.83,109.73 JP17.1
LCDSEG19: length 64.5
  TOP w0.127: v1(62.23,129.67) 62.99,129.67 63.91,128.75 U5.16 ; SB36.1 50.29,104.78 JP18.1 51.82,109.22 60.45,109.22 v1(60.96,108.71)
  BOTTOM w0.127: CN10.29 63.25,87.22 63.25,93.47 62.04,94.68 62.04,106.11 60.96,107.19 v1(60.96,108.71) 60.71,108.97 60.71,119.89 61.47,120.65 61.47,125.48 60.33,126.62 60.33,127.89 62.1,129.67 v1(62.23,129.67)
LCDSEG20: length 50.1
  TOP w0.127: v1(61.21,129.79) 61.59,130.18 62.93,130.18 63.85,129.25 U5.17
  BOTTOM w0.127: CN10.27 61.21,87.73 61.21,98.68 60.33,99.57 60.33,120.27 61.09,121.03 61.09,125.35 59.94,126.49 59.94,128.52 v1(61.21,129.79)
LCDSEG21: length 81.9
  TOP w0.127: v1(55.37,129.67) 60.33,129.67 61.09,130.43 63.17,130.43 63.84,129.75 U5.18
  BOTTOM w0.127: v1(55.37,129.67) 55.75,129.29 55.75,120.02 52.2,116.46 51.05,116.46 48.01,113.41 48.01,103.89 49.28,102.62 49.28,97.41 43.56,91.69 43.56,85.09 35.81,77.34 35.81,69.47 36.83,68.45 CN14.9
LCDSEG22: length 76.6
  TOP w0.127: U5.33 59.65,133.82 58.55,132.72 v1(58.29,132.72)
  BOTTOM w0.127: CN14.11 40.51,69.56 40.51,80.01 45.97,85.47 45.97,92.71 50.23,96.96 50.23,103.7 48.77,105.16 48.77,112.52 51.82,115.57 52.32,115.57 56.52,119.76 56.52,130.94 v1(58.29,132.72)
LCDSEG23: length 74.3
  TOP w0.127: v1(58.29,133.6) 58.67,133.6 59.15,134.08 U5.34
  BOTTOM w0.127: v1(58.29,133.6) 58.8,133.1 58.8,132.46 56.9,130.56 56.9,119.38 56.26,118.75 56.26,110.74 55.5,109.98 55.5,101.6 48.01,94.11 48.01,84.84 42.8,79.63 42.8,69.31 CN14.13
LCDSEG24: length 103.4
  TOP w0.127: v1(46.99,131.06) 46.74,130.81 46.74,130.56 46.48,130.3 45.47,130.3 SB18.1 ; v1(21.72,78.36) 21.84,78.23 44.8,78.23 45.72,77.31 45.72,69.69 CN14.15
  BOTTOM w0.127: v1(21.72,78.36) 21.34,78.74 21.34,82.19 20.7,82.83 20.7,84.18 21.25,84.72 21.25,95.29 25.46,99.5 25.46,101.69 27.72,103.95 27.72,109.26 34.42,115.95 34.42,116.59 37.72,119.89 37.72,124.84 40.89,128.02 40.89,129.41 43.05,131.57 46.48,131.57 v1(46.99,131.06)
LCDSEG25: length 94.8
  TOP w0.127: CN14.17 46.1,69.37 46.1,77.47 44.96,78.61 22.48,78.61 v1(21.84,79.25) ; 43.43,129.16 v1(41.91,129.16)
  BOTTOM w0.127: v1(21.84,79.25) 21.72,79.38 21.72,82.3 21.08,82.93 21.08,84.07 21.59,84.58 21.59,95 25.93,99.34 25.93,101.5 28.07,103.63 28.07,108.97 34.92,115.82 34.92,116.46 38.1,119.63 38.1,124.71 41.91,128.52 v1(41.91,129.16)
LCDSEG26: length 71
  TOP w0.127: v1(58.42,125.73) 50.8,125.73 50.28,126.25 U5.65
  BOTTOM w0.127: CN14.19 48.51,69.5 48.51,80.39 50.55,82.42 50.55,95.25 56.39,101.09 56.39,109.47 57.15,110.24 57.15,118.49 57.66,119 57.66,124.97 v1(58.42,125.73)
LCDSEG27: length 68.4
  TOP w0.127: v1(58.42,124.84) 57.91,125.35 50.67,125.35 50.27,125.75 U5.66
  BOTTOM w0.127: v1(58.42,124.84) 58.29,124.71 58.29,110.11 57.15,108.97 57.15,100.58 53.21,96.65 53.21,69.56 CN14.21
LCDSEG28: length 75.4
  TOP w0.127: U5.55 50.74,131.25 51.31,130.68 58.17,130.68 v1(58.67,131.19)
  BOTTOM w0.127: v1(58.67,131.19) 58.8,131.06 58.8,126.11 59.18,125.73 59.18,124.46 58.67,123.95 58.67,109.73 57.53,108.58 57.53,97.66 53.59,93.73 53.59,69.5 CN14.23
LCDSEG29: length 76.2
  TOP w0.127: U5.56 50.6,130.75 51.05,130.3 58.8,130.3 v1(59.56,131.06)
  BOTTOM w0.127: v1(59.56,131.06) 59.18,130.68 59.18,126.24 60.33,125.09 60.33,121.67 59.44,120.78 59.44,104.65 58.55,103.76 58.55,96.39 56.01,93.85 56.01,69.63 CN14.25
LCDSEG30: length 115.2
  TOP w0.127: CN14.27 59.72,67.34 59.18,66.8 24.64,66.8 v1(22.35,69.09) ; U5.57 48.56,130.25 48.51,130.3 47.74,130.3 v1(47.24,129.81)
  BOTTOM w0.127: v1(47.24,129.81) 44.85,129.81 39.24,124.21 39.24,117.47 36.45,114.68 35.31,114.68 29.21,108.58 29.21,103.25 28.22,102.26 28.22,99.72 26.16,97.66 26.16,95.94 22.73,92.51 22.73,69.6 22.35,69.22 v1(22.35,69.09)
LCDSEG31: length 118.9
  TOP w0.127: v1(48.13,129.79) 48.17,129.75 U5.58 ; CN14.29 62.26,67.85 60.83,66.42 24.38,66.42 22.48,68.33 v1(22.35,68.33)
  BOTTOM w0.127: v1(22.35,68.33) 22.1,68.33 21.84,68.58 21.84,69.6 22.35,70.1 22.35,92.81 25.76,96.22 25.76,97.89 27.9,100.04 27.9,102.43 28.83,103.35 28.83,108.71 35.94,115.82 35.94,116.2 38.86,119.13 38.86,124.33 44.96,130.43 47.88,130.43 48.13,130.18 v1(48.13,129.79)
LCDSEG32: length 122.5
  TOP w0.127: CN14.31 62.39,66.04 24.13,66.04 23.37,65.28 v1(23.24,65.28) ; U5.59 47.59,129.25 47.24,128.91 v1(47.24,128.78)
  BOTTOM w0.127: v1(23.24,65.28) 23.11,65.41 23.11,92.38 26.57,95.83 26.57,97.43 28.65,99.52 28.65,102.16 29.51,103.02 29.51,107.49 30.23,108.2 32.34,108.2 34.5,110.36 35.69,110.36 36.58,111.25 36.58,114.25 39.62,117.3 39.62,124.08 44.32,128.78 v1(47.24,128.78)
LCDSEG33: length 125.8
  TOP w0.127: v1(23.37,64.39) 24.69,65.71 64.6,65.71 CN14.33 ; U5.60 v1(48.13,128.75)
  BOTTOM w0.127: v1(48.13,128.75) 48.13,128.65 47.75,128.27 44.32,128.27 40.01,123.95 40.01,117.17 36.96,114.12 36.96,111.12 35.81,109.98 34.67,109.98 32.51,107.82 30.35,107.82 29.84,107.31 29.84,102.74 29.08,101.98 29.08,99.31 28.3,98.53 28.3,96.93 23.5,92.13 23.5,65.79 23.88,65.41 23.88,64.9 v1(23.37,64.39)
LCDSEG34: length 123.6
  TOP w0.127: CN14.35 69.88,66.71 68.45,65.28 25.4,65.28 24.79,64.67 v1(24.79,64.59) ; U5.61 47.81,128.25 v1(47.24,127.68)
  BOTTOM w0.127: v1(47.24,127.68) 47.17,127.68 43.43,123.95 43.43,121.67 41.02,119.25 41.02,117.22 37.59,113.79 37.59,110.87 35.94,109.22 35.05,109.22 32.64,106.81 32.64,103.61 31.09,102.06 31.09,100.18 29.07,98.16 29.07,96.25 24.26,91.44 24.26,66.17 24.79,65.63 v1(24.79,64.59)
LCDSEG35: length 123.2
  TOP w0.127: U5.62 48.26,127.75 v1(48.13,127.63) ; v1(25.63,64.62) 25.91,64.9 68.96,64.9 72.42,68.36 CN14.37
  BOTTOM w0.127: v1(48.13,127.63) 48.12,127.63 47.24,126.75 46.74,126.75 43.81,123.83 43.81,121.54 41.4,119.13 41.4,117.09 37.97,113.67 37.97,110.74 34.67,107.44 34.67,104.78 31.52,101.63 31.52,100.1 30.53,99.11 30.53,97 24.64,91.11 24.64,66.29 25.63,65.3 v1(25.63,64.62)
LCDSEG36: length 57.8
  TOP w0.127: v1(62.61,116.33) 61.59,117.35 61.59,119.47 U5.97
  BOTTOM w0.127: v1(62.61,116.33) 62.23,115.95 62.23,107.31 63.12,106.43 63.12,95.25 66.04,92.33 66.04,84.07 76.02,74.09 76.02,69.51 CN14.39
LCDSEG37: length 58.1
  TOP w0.127: v1(62.61,117.22) 62.36,117.22 61.98,117.6 61.98,118.49 62.15,118.66 U5.98
  BOTTOM w0.127: CN14.41 76.45,69.5 76.45,74.3 66.42,84.33 66.42,93.47 63.5,96.39 63.5,106.81 62.61,107.7 62.61,115.19 63.12,115.7 63.12,116.71 v1(62.61,117.22)
LCDSEG38: length 67.3
  TOP w0.127: U5.1 65.69,121.25 67.06,119.89 67.06,118.87 68.71,117.22 v1(69.22,117.22)
  BOTTOM w0.127: v1(69.22,117.22) 69.22,116.33 73.41,112.14 76.83,112.14 81.79,107.19 81.79,94.36 86.61,89.53 86.61,84.96 81.03,79.38 81.03,69.44 CN14.43
LCDSEG39: length 68.2
  TOP w0.127: U5.2 65.7,121.75 67.44,120.02 67.44,119.13 68.71,117.86 69.6,117.86 v1(70.23,117.22)
  BOTTOM w0.127: v1(70.23,117.22) 70.23,115.95 73.41,112.78 76.83,112.78 82.3,107.31 82.3,94.61 87,89.92 87,84.58 81.53,79.12 81.53,69.47 82.55,68.45 CN14.45
LED_STLINK: length 32.4
  TOP w0.127: R209.1 R204.1 v1(53.72,23.88) ; v1(44.07,36.32) 43.68,35.94 U24.30
  BOTTOM w0.127: v1(44.07,36.32) 43.69,35.94 43.69,29.46 48.77,24.38 53.21,24.38 v1(53.72,23.88)
LPUART_RTS_3V3: length 17.5
  TOP w0.127: v1(94.87,95) 95,95.12 96.24,95.12 U12.6 ; U8.14 95.84,108.71 94.65,108.71 94.49,108.87 v1(94.36,108.87)
  BOTTOM w0.127: v1(94.87,95) 95.38,95.5 95.38,107.86 v1(94.36,108.87)
MFX_SWCLK: length 12.9
  TOP w0.127: CN19.3 73.15,18.49 73.15,24.89 71.66,26.38 U25.37
MFX_SWDIO: length 10.8
  TOP w0.127: CN19.1 69.98,17.85 69.98,24.38 69.06,25.3 U25.34
MICROB_N: length 6.5
  TOP w0.155: 10.29,149.1 8.97,149.1 8.83,148.96 U10.3 U10.4 6.74,148.96 6.6,149.1 6.22,149.1 5.84,148.72 5.11,148.72 4.98,148.86 CN9.2
MICROB_P: length 6.5
  TOP w0.155: 10.29,147.83 8.99,147.83 8.86,147.96 U10.1 U10.6 6.87,147.96 6.73,147.83 6.22,147.83 5.71,148.34 5.11,148.34 4.98,148.21 CN9.3
NETB2_2: length 13
  TOP w0.127: R215.1 70.48,8.38 R214.1 70.04,9.97 B2.3 B2.2
NETB3_1: length 43.1
  TOP w0.127: U25.20 61.84,29.98 61.47,30.35 58.8,30.35 58.55,30.1 58.55,27.3 59.31,26.54 62.1,26.54 62.99,25.65 62.99,21.21 64.9,19.3 64.9,12.7 65.53,12.06 73.41,12.06 74.55,10.92 74.55,7.37 75.69,6.22 76.63,6.22 B3.1
NETB3_2: length 54.4
  TOP w0.127: U25.18 58.54,30.98 57.66,30.1 57.66,27.05 58.93,25.78 61.72,25.78 61.98,25.53 61.98,21.21 64.14,19.05 64.14,12.32 65.15,11.3 72.39,11.3 73.41,10.29 73.41,6.86 77.22,3.05 78.87,3.05 80.26,4.45 80.26,5.33 79.38,6.22 78.61,6.22 B3.2
NETB3_3: length 46.6
  TOP w0.127: U25.19 61.72,30.48 61.59,30.61 58.67,30.61 58.17,30.1 58.17,27.05 59.05,26.16 61.85,26.16 62.48,25.53 62.48,21.21 64.52,19.18 64.52,12.57 65.41,11.68 72.71,11.68 74.04,10.35 74.04,7.11 76.96,4.19 78.56,4.19 B3.3
NETB3_4: length 27
  TOP w0.127: U25.39 72.36,28.98 72.64,28.7 72.64,25.91 79.5,19.05 79.5,10.16 81.15,8.51 82.88,8.51 B3.4
NETB3_5: length 3.9
  TOP w0.127: R203.2 83.31,10.92 B3.5
NETB3_6: length 23.1
  TOP w0.127: U25.40 72.37,29.48 73.15,28.7 73.15,26.16 81.15,18.16 81.15,10.86 B3.6
NETC2_2: length 4.1
  TOP w0.127: R8.1 C2.2 R7.2
NETC4_2: length 1.9
  TOP w0.127: SB7.2 C4.2
NETC5_2: length 1.8
  TOP w0.127: C5.2 66.93,144.4
NETC6_1: length 10.5
  TOP w0.127: R11.1 105.03,149.22 105.03,147.57 105.99,146.61 U3.2 108.13,146.61 C6.1 R14.2 R15.2
NETC6_2: length 5.8
  TOP w0.127: U3.1 107.74,145.96 108.08,146.3 C6.2 ; R20.2 C6.2 ; C6.2 R14.1
NETC7_1: length 10.2
  TOP w0.127: R16.1 R17.2 C7.1 100,147.26 U3.6 103.83,147.26 104.27,147.7 104.27,149.22 R11.2
NETC7_2: length 22.1
  TOP w0.127: R33.2 v1(110.87,137.67) ; U3.7 102.36,146.56 v1(100.84,146.56) 99.95,146.56 C7.2 R17.1
  BOTTOM w0.127: v1(100.84,146.56) 100.97,146.56 101.73,145.8 107.82,145.8 110.87,142.75 v1(110.87,137.67)
NETC10_2: length 6.4
  TOP w0.127: R25.2 C10.2 53.34,142.88 52.07,144.15 52.07,145.92 TP3.1
NETC11_2: length 6.3
  TOP w0.127: R26.2 C11.2 54.1,143.51 54.1,145.67 TP4.1
NETC12_2: length 9.5
  TOP w0.127: TP2.1 56.45,147.76 56.45,146.24 55.63,145.41 55.63,143.51 C12.2 R27.2
NETC15_2: length 4.1
  TOP w0.127: R28.2 C15.2 R29.1
NETC16_1: length 4.6
  TOP w0.127: U4.7 100.64,139.63 C16.1 R31.1
NETC16_2: length 5.8
  TOP w0.127: U4.6 99.77,140.28 C16.2 R31.2 R30.1
NETC19_1: length 4.4
  TOP w0.127: R38.1 103.63,133.6 C19.1 103.63,136.78 R34.1
NETC22_2: length 1.9
  TOP w0.127: 43.43,133.35 42.8,133.35 C22.2
NETC25_1: length 11.9
  TOP w0.203: X1.1 82.42,128.91 78.11,128.91 77.47,128.27 C25.1 74.42,129.54 R42.2
NETC26_2: length 1.5
  TOP w0.127: C26.2 SB24.1
NETC30_1: length 4.1
  TOP w0.203: X2.1 78.36,123.7 77.98,123.32 C30.1 74.65,123.32 R48.1
NETC34_1: length 3.9
  TOP w0.203: R49.1 C34.1 78.1,121.67 X2.2
NETC35_2: length 11.3
  TOP w0.127: R50.2 C35.2 74.04,119.13 80.52,119.13 TP8.1
NETC38_1: length 2.2
  TOP w0.127: C38.1 15.66,112.43 U7.1
NETC38_2: length 3.4
  TOP w0.127: C38.2 15.22,111.78 U7.2
NETC39_1: length 2.1
  TOP w0.127: U7.27 26.31,111.78 C39.1
NETC41_1: length 3.2
  TOP w0.127: R60.2 C41.1 38.35,111.63 38.29,111.7 U6.1
NETC42_1: length 2.2
  TOP w0.127: U7.3 15.63,111.13 C42.1
NETC45_1: length 2.1
  TOP w0.127: C45.1 26.31,109.83 U7.24
NETC45_2: length 6.3
  TOP w0.127: U7.28 25.82,112.43 26.04,112.65 v1(26.04,113.16) ; C45.2 27.81,109.98 v1(27.56,110.24)
  BOTTOM w0.127: v1(27.56,110.24) 27.56,110.49 27.3,110.74 27.3,111.89 v1(26.04,113.16)
NETC46_2: length 13.8
  TOP w0.127: SB33.1 R67.1 TP14.1 C46.2 CN8.1 42.04,100.71 39.62,98.3 SB30.2
NETC47_1: length 11.3
  TOP w0.127: R54.2 61.21,106.81 59.18,108.84 56.9,108.84 R64.1 55.88,107.82 C47.1 55.88,105.27 U11.3
NETC50_1: length 2.8
  TOP w0.127: C50.1 86,102.9 U8.24
NETC50_2: length 10.1
  TOP w0.127: C50.2 84.2,102.87 83.57,102.23 83.57,99.69 84.07,99.19 86.49,99.19 87.6,100.3 U8.28
NETC51_1: length 2.5
  TOP w0.127: U8.3 98.04,101.6 C51.1
NETC53_1: length 2.5
  TOP w0.127: C53.1 98.01,100.3 U8.1
NETC53_2: length 3.8
  TOP w0.127: U8.2 97.52,100.95 97.79,101.22 98.68,101.22 C53.2
NETC55_1: length 3.1
  TOP w0.127: U8.27 86.59,100.95 C55.1
NETC57_1: length 4.9
  TOP w0.127: R76.1 R73.2 60.83,100.08 C57.1 57.9,100.08 U9.1
NETC58_1: length 5.7
  TOP w0.127: SB32.1 R54.1 C58.1 58.55,103.89 57.59,102.93 U11.5
NETC59_1: length 3.2
  TOP w0.127: JP2.3 83.82,141.48 C59.1
NETC61_2: length 94.3
  TOP w0.127: CN13.5 18.77,67.98 20.95,65.79 20.95,64.01 22.23,62.74 26.04,62.74 26.42,62.36 26.42,55.88 27.3,54.99 C61.2 L4.2 30.61,56.64 32.26,56.64 32.51,56.39 32.51,55.12 33.15,54.48 33.15,50.93 35.05,49.02 49.91,49.02 51.18,47.75 84.58,47.75 88.77,51.94 89.15,51.94 R75.1
NETC62_2: length 92.9
  TOP w0.127: R135.2 88.9,52.96 88.9,52.58 84.45,48.13 51.44,48.13 50.16,49.4 35.43,49.4 33.53,51.31 33.53,56.64 32.77,57.4 32.77,59.94 L11.2 C62.2 30.23,60.96 30.23,62.1 29.21,63.12 22.48,63.12 21.46,64.14 21.46,65.91 18.92,68.45 17.53,68.45 15.8,70.18 CN13.3
NETC63_1: length 5.4
  TOP w0.127: U9.5 57.72,98.1 58.29,98.68 C63.1 R73.1 SB31.1
NETC66_2: length 7.4
  TOP w0.254: U14.6 5.05,84.94 5.84,85.72 C66.2 R92.2 7.37,83.95 10.29,83.95
NETC74_1: length 21.1
  TOP w0.508: U16.3 20.51,58.61 20.98,59.08 20.98,60.05 20.51,60.51 U16.1 17.84,60.51 C74.1 17.02,59.69 15.24,59.69 13.34,57.78 11.22,57.78 D6.2 D5.2 D4.2 D3.2
NETC75_1: length 2
  TOP w0.127: C75.1 21.59,58.29 21.91,58.61 U16.4
NETC84_2: length 59
  TOP w0.127: L12.2 C84.2 44.96,56.26 44.96,50.42 45.59,49.78 50.55,49.78 51.82,48.51 84.33,48.51 88.52,52.7 88.52,53.85 R128.1 R72.1
NETC87_1: length 6.4
  TOP w0.356: U21.8 82.38,40.43 C88.1
  TOP w0.508: C88.1 80.9,40.89 C87.1 78.87,40.01 R151.2
NETC89_2: length 3.3
  TOP w0.457: U22.1 91.76,42.22 R150.2
  TOP w0.508: R150.2 C89.2
NETC90_1: length 7.6
  TOP w0.279: 66.06,36.32 U25.9
  TOP w0.508: 66.06,36.32 65.28,37.1 C93.2 63.88,38.1 C90.1 61.59,38.61 L7.2
NETC95_2: length 6.8
  TOP w0.127: U25.7 67.06,35.68 66.67,36.07 C95.2 R155.2 66.67,41.17 D8.1
NETC100_1: length 4.4
  TOP w0.127: U23.3 89.48,34.62 C100.1 R167.1 89.53,32.26 R170.2
NETC102_1: length 7.6
  TOP w0.254: R162.2 81.15,37.08 80.64,36.58 R165.1 81.66,35.05 C102.1 82.1,34.62 U23.6
NETC102_2: length 4.4
  TOP w0.254: U23.7 82.1,33.96 C102.2 81.66,33.53 R165.2 79.63,33.53 R164.2
NETC105_1: length 27.3
  TOP w0.508: 22.69,30.48 Z1.2 ; Z1.2 23.87,31.5 ; Z1.2 25.05,30.48 ; Z1.2 23.87,29.46 ; 22.73,26.61 U27.3 23.38,26.13 ; 22.48,27.74 C105.1 ; C105.1 22.48,28.65 ; C105.1 22.94,28.19
  TOP w1.143: L8.1 6.52,29.5 9.65,32.64 23.24,32.64
NETC105_2: length 25
  TOP w0.508: 21.46,25.65 21.46,26.13 ; 21.46,26.13 20.81,26.13 ; 21.46,26.13 21.46,26.61 ; 5.26,14.3 CN18.2 ; CN18.2 9.83,14.3 ; CN18.2 7.54,13.11 ; CN18.2 7.54,15.5 ; CN18.3 4.45,21.59 ; CN18.3 5.64,19.3 ; CN18.3 4.45,17.02 ; CN18.3 3.25,19.3 ; 21.46,27.74 C105.2 ; C105.2 21.01,28.19 ; C105.2 21.46,28.65 ; 20.07,29.46 Z1.1 ; Z1.1 21.25,30.48 ; Z1.1 18.89,30.48 ; 9.1,28.33 L8.2 ; L8.2 10.27,29.5 ; L8.2 9.1,30.67 ; L8.2 7.94,29.5
NETC110_1: length 10.1
  TOP w0.508: L9.2 C110.1 90.68,24.51 C111.1 92.71,25.4 CN16.13 CN16.14
NETC110_2: length 10
  TOP w0.508: CN16.16 CN16.15 92.46,22.86 C111.2 90.68,23.5 C110.2 L10.2
NETCN1_1: length 2.4
  TOP w0.127: CN1.1 R1.2
NETCN1_3: length 2.4
  TOP w0.127: CN1.3 R2.2
NETCN1_4: length 146.5
  TOP w0.127: v1(19.94,155.19) R3.1 18.54,156.84 17.78,157.61 17.78,163.96 18.29,164.47 CN1.4
  BOTTOM w0.127: v1(19.94,155.19) 30.73,155.19 31.11,154.81 31.11,150.75 36.45,145.41 49.53,145.41 56.01,138.94 58.29,138.94 61.59,135.64 64.39,135.64 67.44,132.59 67.44,117.35 73.28,111.51 75.95,111.51 76.71,110.74 76.71,108.08 77.72,107.06 79.38,107.06 81.41,105.03 81.41,93.98 86.11,89.28 86.11,85.22 80.04,79.15 80.04,70.99
NETCN2_2: length 3.9
  TOP w0.127: R7.1 76.07,147.19 CN2.2
NETCN3_2: length 2.5
  TOP w0.127: CN3.2 R28.1
NETCN4_2: length 2.5
  TOP w0.127: CN4.2 25.02,145.16 R19.2
NETCN5_7: length 23.8
  TOP w0.127: SB23.2 71.75,128.39 v1(72.26,128.91)
  BOTTOM w0.127: CN5.7 85.09,138.43 81.15,134.49 76.83,134.49 72.26,129.92 v1(72.26,128.91)
NETCN5_8: length 27.6
  TOP w0.127: 71.38,127 v1(72.26,127)
  BOTTOM w0.127: CN5.8 91.82,137.54 84.84,137.54 81.41,134.11 76.96,134.11 72.9,130.05 72.9,127.38 72.52,127 v1(72.26,127)
NETCN5_11: length 27.3
  TOP w0.127: SB27.2 v1(72.14,121.67)
  BOTTOM w0.127: CN5.11 83.82,133.35 80.9,130.43 75.18,130.43 74.55,129.79 74.55,123.95 72.26,121.67 v1(72.14,121.67)
NETCN5_12: length 30.2
  TOP w0.127: SB26.2 v1(72.14,123.57)
  BOTTOM w0.127: CN5.12 91.69,134.37 83.31,134.37 81.92,132.97 77.22,132.97 74.17,129.92 74.17,124.71 74.3,124.59 74.3,124.08 74.04,123.83 73.79,123.83 73.41,123.44 72.26,123.44 v1(72.14,123.57)
NETCN5_13: length 5
  TOP w0.127: R39.2 88.77,132.21 CN5.13
NETCN5_24: length 20.6
  TOP w0.127: CN5.24 94.36,119.76 94.36,128.52 93.22,129.67 88.52,129.67 87.5,130.68 R41.2
NETCN6_2: length 24.8
  TOP w0.127: U7.6 14.44,109.18 13.39,110.24 13.39,126.7 12.12,127.97 CN6.2
NETCN6_3: length 23.4
  TOP w0.127: U7.10 14.91,106.58 12.12,109.37 12.12,123.49 CN6.3
NETCN6_6: length 28.5
  TOP w0.127: U7.5 14.35,109.83 13.82,110.36 13.82,127.91 12.37,129.36 CN6.6
